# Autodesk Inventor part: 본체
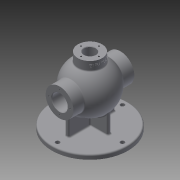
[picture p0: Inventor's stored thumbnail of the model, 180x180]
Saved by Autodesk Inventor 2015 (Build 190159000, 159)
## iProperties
Created: 2020-08
Part Number: 본체
Material: 일반
Document SubType Name: Modeling
Designer: now
Density: 1 g/cm^3
Appearance: 기본값
Mass: 649.105 g
Surface Area: 1342.86 cm^2
Volume: 649.105 cm^3
Author: now
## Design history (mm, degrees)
sketch "스케치1"
  geometry: C1 r 85 at (0, 0); 1 further point
  constraints: 1 centre point, 1 coincident
  dimensions: "d0" = 170 diameter of C1
extrude "돌출1" new body sketch "스케치1" distance "d1" = 10; taper "d2" = 0 deg
sketch "스케치2"
  geometry: L1 (4, 52)-(-4, 52); L2 (-4, 52)-(-4, -52); L3 (-4, -52)-(4, -52); L4 (4, -52)-(4, 52); L5 (4, 52)-(-4, -52); L6 (-4, 52)-(4, -52); C1 r 85 at (0, 0) reference
  constraints: 12 end point, 2 midpoint, 2 parallel, 1 horizontal, 1 perpendicular
  dimensions: "d3" = 104 distance of L3.end L1.start; "d4" = 8 distance of L2.end L3.end
extrude "돌출2" join sketch "스케치2" distance "d5" = 75; taper "d6" = 0 deg
sketch "스케치3"
  geometry: L1 (43, 4)-(-43, 4); L2 (-43, 4)-(-43, -4); L3 (-43, -4)-(43, -4); L4 (43, -4)-(43, 4); L5 (43, 4)-(-43, -4); L6 (-43, 4)-(43, -4); C1 r 85 at (0, 0) reference
  constraints: 12 end point, 2 midpoint, 2 parallel, 1 horizontal, 1 perpendicular
  dimensions: "d7" = 8 distance of L1.end L2.end; "d8" = 86 distance of L2.end L3.end
extrude "돌출3" join sketch "스케치3" distance "d9" = 75; taper "d10" = 0 deg
sketch "스케치4"
  geometry: L1 (85, 10)-(85, 0) reference; L2 (85, 0)-(-85, 0) reference; L3 (-85, 0)-(-85, 10) reference; L4 (-85, 10)-(-52, 10) reference; L5 (-52, 10)-(-52, 85) reference; L6 (-52, 85)-(52, 85) reference; L7 (52, 85)-(52, 10) reference; L8 (52, 10)-(85, 10) reference; L9 (68, 116)-(68, 85); L10 (68, 85)-(-68, 85); L11 (-68, 85)-(-68, 116); L12 (-68, 116)-(-42.988, 116); L13 (42.988, 116)-(68, 116); A1 r 53 centre (0, 85) between (42.988, 116) and (-42.988, 116); 2 further points
  constraints: 10 end point, 3 parallel, 2 horizontal, 2 midpoint, 2 perpendicular, 2 point on circle, 1 centre point, 1 vertical alignment
  dimensions: "d12" = 31 distance of L10.end L11.end; "d13" = 53 radius of A1; "d14" = 136 distance of L11.end L9.start; "d17" = 85 distance of point (0, 0) A1.centre; "d18" = 31 distance between parallel lines of L10 L13
revolve "회전1" sketch "스케치4" stored, may be unused: angle "d19" = 90 deg
node "작업 평면1"
sketch "스케치5"
  geometry: C1 r 27 at (0, 0); 1 further point
  constraints: 1 centre point, 1 coincident
  dimensions: "d21" = 54 diameter of C1
extrude "돌출4" join sketch "스케치5" stored distance "d22" = 75; taper "d23" = 0 deg
sketch "스케치6"
  geometry: L1 (68, 54)-(52, 54) reference; L2 (52, 54)-(52, 10) reference; L3 (52, 10)-(85, 10) reference; L4 (85, 10)-(85, 0) reference; L5 (85, 0)-(-85, 0) reference; L6 (-85, 0)-(-85, 10) reference; L7 (-85, 10)-(-52, 10) reference; L8 (-52, 10)-(-52, 54) reference; L9 (-52, 54)-(-68, 54) reference; L10 (-68, 54)-(-68, 116) reference; L11 (-68, 116)-(-42.988, 116) reference; L12 (-27, 130.607)-(-27, 150) reference; L13 (-27, 150)-(27, 150) reference; L14 (27, 150)-(27, 130.607) reference; L15 (42.988, 116)-(68, 116) reference; L16 (68, 116)-(68, 54) reference; L17 (-68, 54)-(-68, 116) reference; L18 (-68, 85)-(68, 85); L19 (68, 54)-(68, 116) reference; L20 (-43, 85)-(43, 85); L21 (42.988, 54.259)-(42.988, 116) reference; A1 r 53 centre (0, 85) between (-27, 130.607) and (-42.988, 116) reference; A2 r 53 centre (0, 85) between (42.988, 116) and (27, 130.607) reference; A3 r 43 centre (0, 85) between (43, 85) and (-43, 85); 1 further point
  constraints: 4 end point, 2 midpoint, 2 point on circle, 2 point on line, 1 centre point, 1 coincident, 1 perpendicular
  dimensions: "d25" = 43 radius of A3
revolve "회전2" sketch "스케치6" stored, may be unused: angle "d26" = 90 deg
sketch "스케치7"
  geometry: C1 r 31 at (0, 0) reference; C2 r 17.5 at (0, 0); 1 further point
  constraints: 1 centre point, 1 coincident
  dimensions: "d27" = 35 diameter of C2
extrude "돌출5" cut sketch "스케치7" distance "d28" = 16; taper "d29" = 0 deg
sketch "스케치9"
  geometry: C1 r 31 at (0, 0) reference; 1 further point
hole "구멍1" sketch "스케치9" at (0, 0) diameter "d33" = 35; stored, may be unused: countersink angle "d37" = 90 deg, drill point angle "d39" = 118 deg; dims "d34" = 6, "d35" = 4, "d36" = 2, "d38" = 8
sketch "스케치10"
  geometry: C1 r 27 at (0, 0) reference; C2 r 13 at (0, 0)
  constraints: 1 centre point, 1 coincident
  dimensions: "d40" = 26 diameter of C2
extrude "돌출7" cut sketch "스케치10" stored distance "d41" = 1.75; taper "d42" = 0 deg
sketch "스케치11"
  geometry: C1 r 17.5 at (0, 0) reference; 2 further points
  constraints: 1 vertical alignment
  dimensions: "d43" = 24 distance of C1.centre point (0, 24)
hole "구멍2" sketch "스케치11" at (0, 24) diameter "d44" = 3.242; stored, may be unused: countersink angle "d48" = 90 deg, drill point angle "d50" = 118 deg; dims "d45" = 12, "d46" = 4, "d47" = 2, "d49" = 15
sketch "스케치12"
  geometry: C1 r 13 at (0, 0) reference; 1 further point
  constraints: 1 horizontal alignment
  dimensions: "d54" = 20 distance of C1.centre point (-20, 0)
hole "구멍3" sketch "스케치12" at (-20, 0) diameter "d55" = 3.242; stored, may be unused: countersink angle "d59" = 90 deg, drill point angle "d61" = 118 deg; dims "d56" = 12, "d57" = 4, "d58" = 2, "d60" = 15
sketch "스케치13"
  geometry: C1 r 85 at (0, 0) reference; A1 r 72.5 centre (0, 0) between (-72.5, 0) and (0, 72.5); 2 further points
  constraints: 4 point on circle, 2 horizontal alignment, 2 vertical alignment, 1 centre point, 1 coincident
  dimensions: "d65" = 145 diameter of A1
hole "구멍4" sketch "스케치13" at (-72.5, 0), (0, 72.5), (0, -72.5), (72.5, 0) diameter "d66" = 9; stored, may be unused: countersink angle "d70" = 90 deg, drill point angle "d72" = 118 deg; dims "d67" = 12, "d68" = 4, "d69" = 2, "d71" = 15
chamfer "모따기1" distance "d73" = 1; stored, may be unused: second distance "d74" = 2, angle "d75" = 45 deg
chamfer "모따기2" distance "d76" = 1; stored, may be unused: second distance "d77" = 2, angle "d78" = 45 deg
chamfer "모따기3" distance "d79" = 1; stored, may be unused: second distance "d80" = 2, angle "d81" = 45 deg
fillet "모깎기1" dims "d82" = 3
fillet "모깎기2" dims "d83" = 3
fillet "모깎기3" dims "d84" = 3
fillet "모깎기4" dims "d85" = 3
fillet "모깎기5" dims "d86" = 3
fillet "모깎기6" dims "d87" = 3
node "작업 평면2"
sketch "스케치14"
  geometry: L1 (68, 100.232)-(68, 69.768) reference; L2 (68, 69.768)-(44.497, 69.768) reference; L3 (4, 36.441)-(4, 13) reference; L4 (7, 10)-(77.427, 10) reference; L5 (80.598, 7)-(80.598, 0) reference; L6 (80.598, 0)-(-80.598, 0) reference; L7 (-80.598, 0)-(-80.598, 7) reference; L8 (-77.427, 10)-(-7, 10) reference; L9 (-4, 13)-(-4, 36.441) reference; L10 (-44.497, 69.768)-(-68, 69.768) reference; L11 (-68, 69.768)-(-68, 100.232) reference; L12 (-68, 100.232)-(-44.497, 100.232) reference; L13 (44.497, 100.232)-(68, 100.232) reference; L14 (0, 150)-(0, 132.286) reference; L15 (27, 150)-(-27, 150) reference; L16 (27, 150)-(-27, 150) reference; L17 (-27, 132.286)-(27, 132.286) reference; C1 r 33.466 at (0, 85) reference; A1 r 45.607 centre (0, 85) between (6.625, 39.877) and (42.113, 67.494) reference; A2 r 3 centre (7, 13) between (4, 13) and (7, 10) reference; A3 r 3 centre (-7, 13) between (-7, 10) and (-4, 13) reference; A4 r 45.607 centre (0, 85) between (-42.113, 67.494) and (-6.625, 39.877) reference; A5 r 45.607 centre (0, 85) between (-8.784, 129.753) and (-42.113, 102.506) reference; A6 r 45.607 centre (0, 85) between (42.113, 102.506) and (8.784, 129.753) reference; 2 further points
  constraints: 11 other
  dimensions: "d89" = 27 horizontal distance of L15.end point (0, 141); "d90" = 9 vertical distance of L15.end point (0, 141)
feature "엠보싱1" sketch "스케치14" dims "d7" = 8, "d8" = 86, "d91" = 0.5, "d92" = 0
node "작업 평면3"
sketch "스케치15"
  geometry: L1 (-6.196, 75)-(-63.403, 75) reference; L2 (-67.238, 78)-(-67.238, 85) reference; L3 (-67.238, 85)-(67.238, 85) reference; L4 (67.238, 85)-(67.238, 78) reference; L5 (63.403, 75)-(6.196, 75) reference; L6 (1, 72)-(-1, 72) reference; L7 (-1, 72)-(-1, 33.985) reference; L8 (1, 72)-(1, 33.985) reference; C1 r 17.5 at (0, 0) reference; C2 r 18.5 at (0, 0); A1 r 31 centre (0, 0) between (-5.649, 30.481) and (5.649, 30.481) reference; A2 r 34 centre (0, 0) between (1, 33.985) and (-1, 33.985) reference; 1 further point
  constraints: 1 centre point, 1 coincident, 6 other
  dimensions: "d94" = 37 diameter of C2
extrude "돌출8" cut sketch "스케치15" distance "d95" = 1.75; taper "d96" = 0 deg
node "솔리드1"
pattern_circular "원형 패턴1" dims angle "d52" = 360 deg
mirror "대칭1"
pattern_circular "원형 패턴2" dims angle "d63" = 360 deg
node "투영된 루프1"
node "절단 모서리 투영1"
node "절단 모서리 투영2"
node "절단 모서리 투영3"
node "절단 모서리 투영4"
other parameters: "d88" = 27, "d93" = -16
